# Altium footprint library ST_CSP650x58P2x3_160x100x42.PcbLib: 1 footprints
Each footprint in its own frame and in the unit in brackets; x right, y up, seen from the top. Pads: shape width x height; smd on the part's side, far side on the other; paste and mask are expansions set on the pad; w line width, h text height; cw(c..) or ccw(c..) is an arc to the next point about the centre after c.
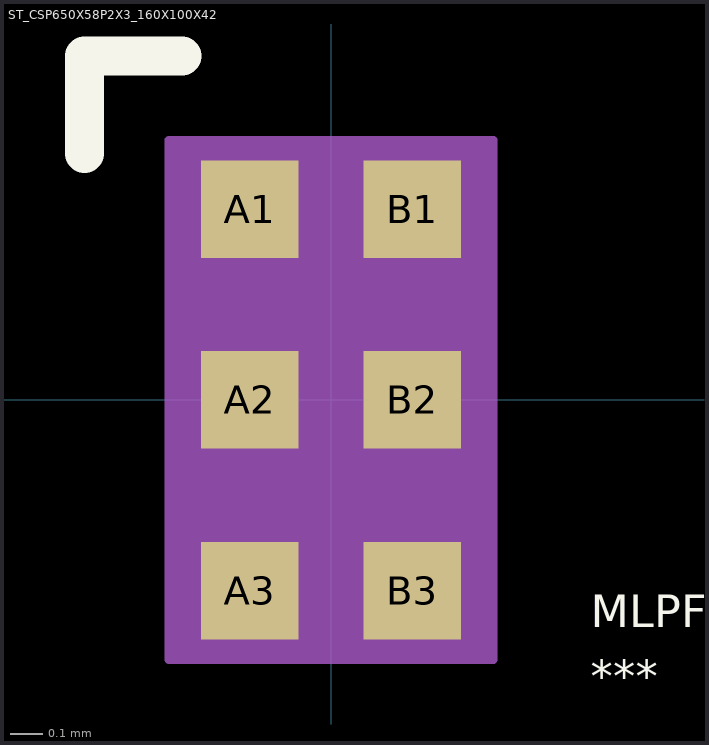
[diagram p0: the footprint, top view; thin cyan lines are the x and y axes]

## ST_CSP650X58P2X3_160X100X42 [mm] "ST_CSP650X58P2X3_160X100X42"
pads (6):
  rect 0.3x0.3 smd paste-0.05 mask-0.05: A1(-0.25,0.587) A2(-0.25,0) A3(-0.25,-0.587) B1(0.25,0.587) B2(0.25,0) B3(0.25,-0.587)
Top Overlay:
  lines w0.12: -0.759,0.759 -0.759,1.059 -0.459,1.059
  text ".Designator" at 0.8,-0.5 h0.1
  text "MLPF-WB55-01E3" at 0.8,-0.7 h0.1
  text "***" at 0.8,-0.9 h0.1
Mechanical 5:
  text "A1" at -0.655,0.55 h0.1
  text "A3" at -0.697,-0.657 h0.1
  text "A2" at -0.697,-0.06 h0.1
  text "B1" at 0.545,0.555 h0.1
  text "B2" at 0.54,-0.055 h0.1
  text "B3" at 0.535,-0.64 h0.1
Mechanical 6:
  lines w0.025: -0.5,-0.8 -0.5,0.8 0.5,0.8 0.5,-0.8 -0.5,-0.8
  text "MLPF-WB55-01E3" at 0.8,0.6 h0.1
  text "***" at 0.8,0.4 h0.1
Mechanical 7:
  region: -0.5,0.8 -0.5,-0.8 0.5,-0.8 0.5,0.8
3D body: height 0.45, standoff 0, extent -0.5,-0.8 0.5,0.8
